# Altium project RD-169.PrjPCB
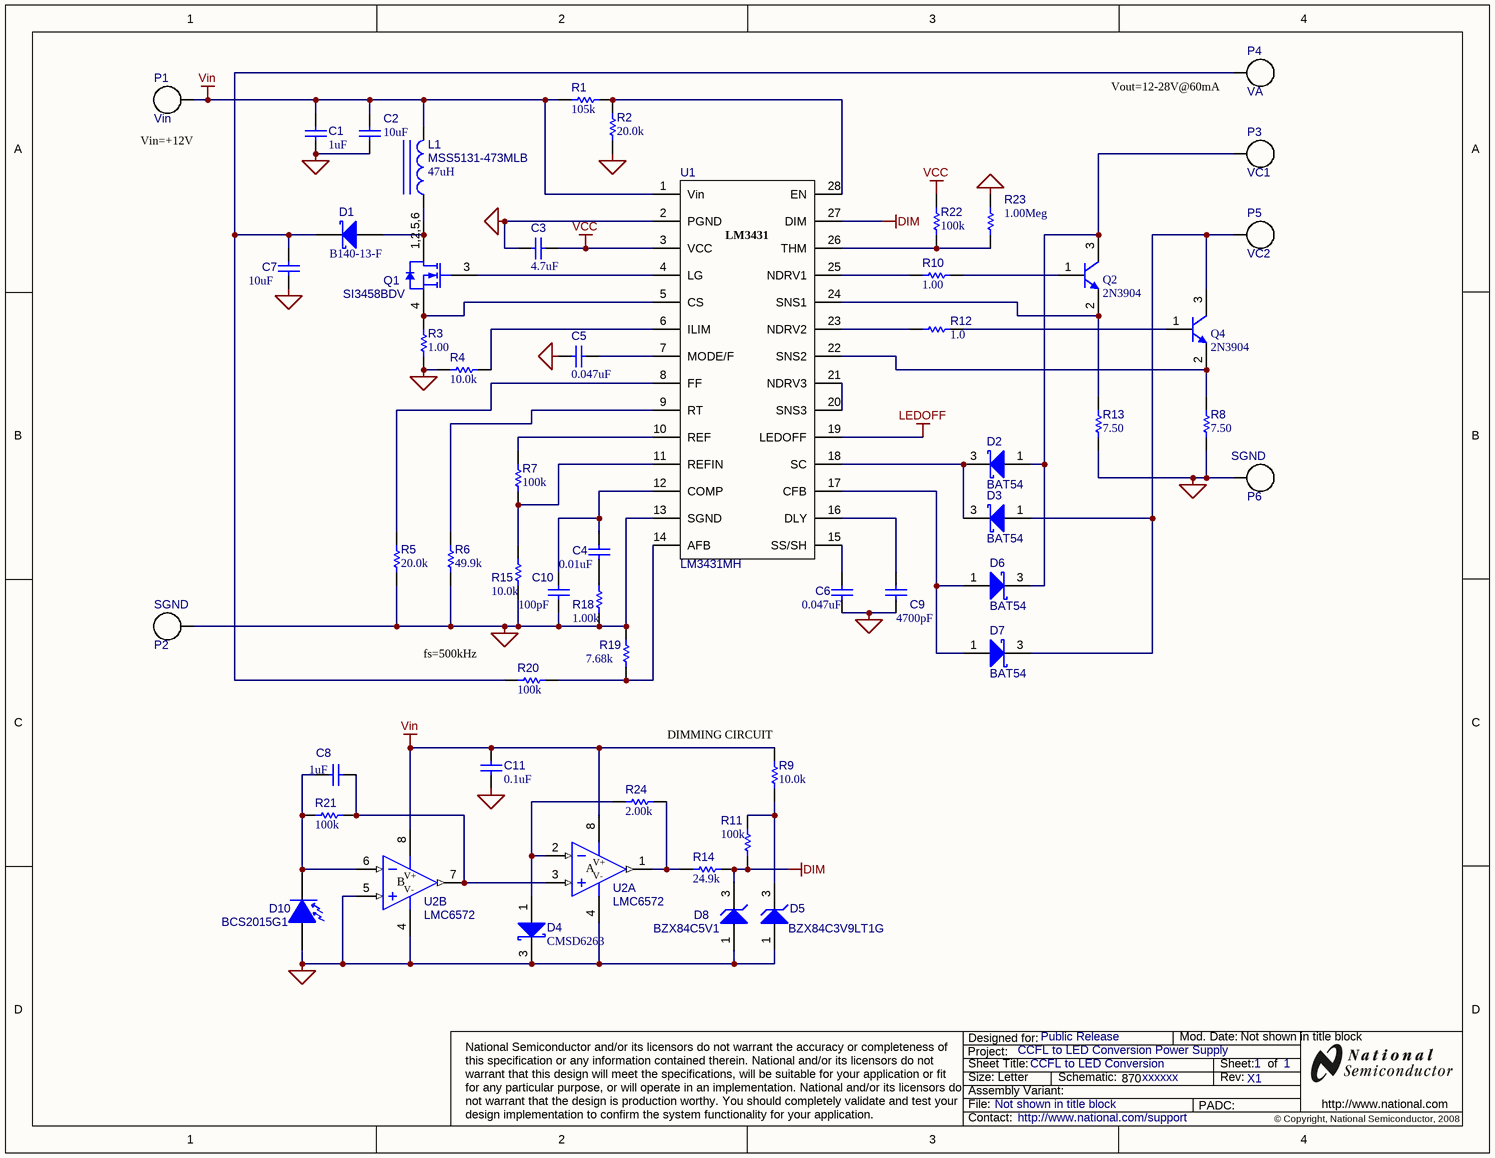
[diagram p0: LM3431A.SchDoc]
TechSupport: http://www.national.com/support; SCH_Rev: X1; PRJ_Title: CCFL to LED Conversion Power Supply; PRJ_Customer: Public Release; PRJ_BasePN: xxxxxx; PCB_MinorRev: -001
1 sheet, 54 parts. Net scope: global (net labels, ports and power ports of the same name join across sheets).

## Sheet LM3431A.SchDoc: CCFL to LED Conversion
size Letter; Date: Not shown in title block; ApprovedBy: Not shown in title block; CheckedBy: Not shown in title block; Author: Not shown in title block; CompanyName: Not shown in title block; DrawnBy: Not shown in title block; Engineer: Not shown in title block; Organization: Not shown in title block; Address1: Not shown in title block; Address2: Not shown in title block; Address3: Not shown in title block; Address4: Not shown in title block; DocumentNumber: 1; Revision: Use project parameter SCH_Rev; SheetNumber: 1; SheetTotal: 1; PageSetup: Record=PageOptions|CenterHorizontal=True|CenterVertical=True|PrintScale=0.97|XCorrection=1.00|YCorrection=1.00|PrintKind=0|BorderSize=5000000|LeftOffset=0|BottomOffset=0|Orientation=2|PaperLength=1000|PaperWidth=1000|Scale=100|PaperSource=15|PrintQuality=600|MediaType=1|DitherType=10|PaperKind=Letter|PrintScaleMode=1

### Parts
C1  value 1uF  [0805]  (hidden comment: C2012X7R1A105K)
C2  value 10uF  [1206]  (hidden comment: C3216X7R1A106M)
C3  value 4.7uF  [1206]  (hidden comment: C3216X5R1A475K)
C4  value 0.01uF  [0805]  (hidden comment: C2012C0G1E103J)
C5  value 0.047uF  [0805]  (hidden comment: C2012X7R2A473K)
C6  value 0.047uF  [0805]  (hidden comment: C2012X7R2A473K)
C7  value 10uF  [1210]  (hidden comment: C3225X7R1E106M)
C8  value 1uF  [0805]  (hidden comment: 0805ZC105MAT2A)
C9  value 4700pF  [0805]  (hidden comment: C2012X7R2A472M)
C10  value 100pF  [0805]  (hidden comment: C2012C0G1H101J)
C11  value 0.1uF  [0805]  (hidden comment: C2012X7R1H104K)
D1  B140-13-F  [SMA]
D2  BAT54  [SOT-23]
D3  BAT54  [SOT-23]
D4  PartNumber: CMSD6263  [SOT-23]
D5  BZX84C3V9LT1G  [SOT-23]
D6  BAT54  [SOT-23]
D7  BAT54  [SOT-23]
D8  BZX84C5V1  [SOT-23]
D10  BCS2015G1  [SMA]
L1  MSS5131-473MLB  value 47uH  [MSS5131]
P1  Vin  [TESTPOINT]  (no BOM)
P2  SGND  [TESTPOINT]  (no BOM)
P3  VC1  [TESTPOINT]  (no BOM)
P4  VA  [TESTPOINT]  (no BOM)
P5  VC2  [TESTPOINT]  (no BOM)
P6  SGND  [TESTPOINT]  (no BOM)
Q1  SI3458BDV  [TSOP-6]
Q2  2N3904  [SOT-23]
Q4  2N3904  [SOT-23]
R1  value 105k  [0805]  (hidden comment: CRCW0805105kFKEA)
R2  value 20.0k  [0805]  (hidden comment: CRCW080520k0FKEA)
R3  value 1.00  [0805]  (hidden comment: CRCW08051R00FNEA)
R4  value 10.0k  [0805]  (hidden comment: CRCW080510k0FKEA)
R5  value 20.0k  [0805]  (hidden comment: CRCW080520k0FKEA)
R6  value 49.9k  [0805]  (hidden comment: CRCW080549k9FKEA)
R7  value 100k  [0805]  (hidden comment: CRCW0805100kFKEA)
R8  value 7.50  [0805]  (hidden comment: CRCW08057R50FNEA)
R9  value 10.0k  [0805]  (hidden comment: CRCW080510k0FKEA)
R10  value 1.00  [0805]  (hidden comment: CRCW08051R00FNEA)
R11  value 100k  [0805]  (hidden comment: CRCW0805100kFKEA)
R12  value 1.0  [0805]  (hidden comment: CRCW08051R00JNEA)
R13  value 7.50  [0805]  (hidden comment: CRCW08057R50FNEA)
R14  value 24.9k  [0805]  (hidden comment: CRCW080524k9FKEA)
R15  value 10.0k  [0805]  (hidden comment: CRCW080510k0FKEA)
R18  value 1.00k  [0805]  (hidden comment: CRCW08051k00FKEA)
R19  value 7.68k  [0805]  (hidden comment: CRCW08057k68FKEA)
R20  value 100k  [0805]  (hidden comment: CRCW0805100kJNEA)
R21  value 100k  [0805]  (hidden comment: CRCW0805100kFKEA)
R22  value 100k  [0805]  (hidden comment: CRCW0805100kFKEA)
R23  value 1.00Meg  [0805]  (hidden comment: CRCW08051M00FKEA)
R24  value 2.00k  [0805]  (hidden comment: CRCW08052k00FKEA)
U1  LM3431MH  [MXA28A]
U2  LMC6572  [M08A]  (parts A,B of 2)

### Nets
DIM: D8.3(K) R11.2 R14.1 U1.27(DIM)
LEDOFF: U1.19(LEDOFF)
NetD4_3: D4.3(K) D5.1(A) D8.1(A) D10.1(A) U2.4(V-) U2.5(IN+)
SGND: C1.2 C2.2 C3.2 C5.2 C6.2 C7.2 C9.2 C10.2 C11.2 P2.1 P6.1 R2.2 R3.2 R4.2 R5.2 R6.2 R8.2 R13.2 R15.2 R18.2 R19.1 R23.1 U1.2(PGND) U1.13(SGND)
VCC: C3.1 R22.1 U1.3(VCC)
Vin: C1.1 C2.1 C11.1 L1.2 P1.1 R1.2 R9.1 U1.1(Vin) U2.8(V+)
NetC4_1: C4.1 C10.1 U1.12(COMP)
NetC4_2: C4.2 R18.1
NetC5_1: C5.1 U1.7(MODE/F)
NetC6_1: C6.1 U1.15(SS/SH)
NetC7_1: C7.1 D1.2(K) P4.1 R20.2
NetC8_1: C8.1 R21.1 U2.3(IN+) U2.7(OUT)
NetC8_2: C8.2 D10.2(K) R21.2 U2.6(IN-)
NetC9_1: C9.1 U1.16(DLY)
NetD1_1: D1.1(A) L1.1 Q1.1,2,5,6(D)
NetD2_1: D2.1(A) D6.3(K) P3.1 Q2.3(C)
NetD2_3: D2.3(K) D3.3(K) U1.18(SC)
NetD3_1: D3.1(A) D7.3(K) P5.1 Q4.3(C)
NetD4_1: D4.1(A) R24.2 U2.2(IN-)
NetD5_3: D5.3(K) R9.2 R11.1
NetD6_1: D6.1(A) D7.1(A) U1.17(CFB)
NetQ1_2: Q1.2(D) Q1.5(D)
NetQ1_3: Q1.3(G) U1.4(LG)
NetQ1_4: Q1.4(S) R3.1 U1.5(CS)
NetQ2_1: Q2.1(B) R10.1
NetQ2_2: Q2.2(E) R13.1 U1.24(SNS1)
NetQ4_1: Q4.1(B) R12.1
NetQ4_2: Q4.2(E) R8.1 U1.22(SNS2)
NetR1_1: R1.1 R2.1 U1.28(EN)
NetR4_1: R4.1 U1.6(ILIM)
NetR5_1: R5.1 U1.8(FF)
NetR6_1: R6.1 U1.9(RT)
NetR7_1: R7.1 U1.10(REF)
NetR7_2: R7.2 R15.1 U1.11(REFIN)
NetR10_2: R10.2 U1.25(NDRV1)
NetR12_2: R12.2 U1.23(NDRV2)
NetR14_2: R14.2 R24.1 U2.1(OUT)
NetR19_2: R19.2 R20.1 U1.14(AFB)
NetR22_2: R22.2 R23.2 U1.26(THM)
NetU1_20: U1.20(SNS3) U1.21(NDRV3)

Not connected (* = marked no-connect by the designer): Q1 6(D)

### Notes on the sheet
- (near P4) Vout=12-28V@60mA
- (near P1) Vin=+12V
- (near R20) fs=500kHz
- (near R9) DIMMING CIRCUIT

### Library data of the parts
C1 = C2012X7R1A105K: Capacitor; Manufacturer: TDK; ESR_Ohm: 0.0075; Polarized: N; TaMax_C: 125; TaMin_C: -55; Tolerance_%: 10; Cap_F: 1.0E-6; Value1: 0.0075Ohm; Value2: 10V; Dielectric: X7R; Characteristics: Ceramic, X7R, 10V, 10%
C2 = C3216X7R1A106M: Capacitor; Manufacturer: TDK; ESR_Ohm: 0.0046; Polarized: N; TaMax_C: 125; TaMin_C: -55; Tolerance_%: 20; VDC_V: 10; Cap_F: 10.0E-6; Value1: 0.0046Ohm; Value2: 10V; Dielectric: X7R; Characteristics: Ceramic, X7R, 10V, 20%
C3 = C3216X5R1A475K: Capacitor; Manufacturer: TDK; ESR_Ohm: 0.0036; Polarized: N; TaMax_C: 85; TaMin_C: -55; Tolerance_%: 10; Cap_F: 4.7E-6; Value1: 0.0036Ohm; Value2: 10V; Dielectric: X5R; Characteristics: Ceramic, X5R, 10V, 10%
C4 = C2012C0G1E103J: Capacitor; Manufacturer: TDK; ESR_Ohm: 0.03; Polarized: N; TaMax_C: 125; TaMin_C: -55; Tolerance_%: 5; VDC_V: 25; Cap_F: 10.0E-9; Value1: 0.03Ohm; Value2: 25V; Dielectric: C0G/NP0; Characteristics: Ceramic, C0G/NP0, 25V, 5%
C5 C6 = C2012X7R2A473K: Capacitor; Manufacturer: TDK; ESR_Ohm: 0.0211; Polarized: N; TaMax_C: 125; TaMin_C: -55; Tolerance_%: 10; VDC_V: 100; Cap_F: 47.0E-9; Value1: 0.0211Ohm; Value2: 100V; Dielectric: X7R; Characteristics: Ceramic, X7R, 100V, 10%
C7 = C3225X7R1E106M: Capacitor; Manufacturer: TDK; ESR_Ohm: 0.0027; IRMS_A: 3; Polarized: N; TaMax_C: 125; TaMin_C: -55; Tolerance_%: 20; VDC_V: 25; Cap_F: 10.0E-6; Value1: 0.0027Ohm; Value2: 25V; Dielectric: X7R; Characteristics: Ceramic, X7R, 25V, 20%
C8 = 0805ZC105MAT2A: Capacitor; Manufacturer: AVX; ESR_Ohm: 0.008; Polarized: N; TaMax_C: 125; TaMin_C: -55; Tolerance_%: 20; VDC_V: 10; Cap_F: 1.0E-6; Value1: 0.008Ohm; Value2: 10V; Dielectric: X7R; Characteristics: Ceramic, X7R, 10V, 20%
C9 = C2012X7R2A472M: Capacitor; Manufacturer: TDK; ESR_Ohm: 0.1198; Polarized: N; TaMax_C: 125; TaMin_C: -55; Tolerance_%: 20; VDC_V: 100; Cap_F: 4.7E-9; Value1: 0.1198Ohm; Value2: 100V; Dielectric: X7R; Characteristics: Ceramic, X7R, 100V, 20%
C10 = C2012C0G1H101J: Capacitor; Manufacturer: TDK; Polarized: N; TaMax_C: 125; TaMin_C: -55; Tolerance_%: 5; VDC_V: 50; Cap_F: 100.0E-12; Value1: Ohm; Value2: 50V; Dielectric: C0G/NP0; Characteristics: Ceramic, C0G/NP0, 50V, 5%
C11 = C2012X7R1H104K: Capacitor; Manufacturer: TDK; Polarized: N; TaMax_C: 125; TaMin_C: -55; Tolerance_%: 10; VDC_V: 50; Cap_F: 100.0E-9; Value1: Ohm; Value2: 50V; Dielectric: X7R; Characteristics: Ceramic, X7R, 50V, 10%
D1 = B140-13: Schottky Diode; Manufacturer: Diodes Inc.; RJC_CperW: 20; Vf_V: 0.5; Io_A: 1; Vr_V: 40; TJMax_C: 150; Value: 0.5V; Value1: 1A; Value2: 40V; Characteristics: Vr = 40V, Io = 1A, Vf = 0.5V
D2 D3 D6 D7 = BAT54-7-F: Schottky Barrier Diode; Manufacturer: Diodes Inc.; Vf_V: 0.24; Value: 0.24V; Io_A: 0.2; Value1: 0.2A; Vr_V: 30; Value2: 30V; TJmax_C: 125; RJC_CperW: 0; Characteristics: Vr = 30V, Io = 0.2A, Vf = 0.24V
D4 = BAT46: Schottky Barrier Diode; Manufacturer: Central Semiconductor; Vf_V: 0.24; Value: 0.24V; Io_A: 0.2; Value1: 0.2A; Vr_V: 30; Value2: 30V; TJmax_C: 125; RJC_CperW: 0; Characteristics: Vr = 70V, Vf = 0.41V
D5 = WB_Zener: Manufacturer: ON Semiconductor; CompType: Zener Diode; Value: 3.9V
D8 = WB_Zener: Manufacturer: Diodes, Inc.; PartNumber: BZX84C5V1-7-F; CompType: Zener; Value: 5.1V
D10 = A10190: Light Emitting Diode; Manufacturer: TDK; CompType: Photodiode
L1 = MSS5131-473MLB: Magnetic-Core Inductor; Manufacturer: Coilcraft Inc.; Characteristics: Shielded Drum Core, 0.38A, 0.32 Ohm; Ind_H: 47.0E-6; DCR_Ohm: 0.32; Value1: 0.32Ohm; Imax_A: 0.38; Value2: 0.38A; Material: Ferrite
P1-P6 = WB_TESTPOINT: TEST POINT.  No entry in BOM.
Q1 = SI3458BDV: N-Chan. Mosfet; Manufacturer: Vishay-Siliconix; ChType: N; Value1: 0.21Ohm; QgTyp_nC: 3.5; Value: 60V; Characteristics: -3.6A, 3.5nC, rDS(on) @ 4.5V =0.105
Q2 Q4 = CMPT3904: NPN Bipolar Transistor; Manufacturer: Central Semiconductor; CompType: BJT; PNP: 0; NPN: 1; Vceo_V: 40; Vcesat1_V: 0.2; Value: 0.2V; Value1: 0.2A; Characteristics: NPN, 0.2A, 40V
R1 = CRCW0805105kFKEA: Resistor; Manufacturer: Vishay-Dale; Tolerance_%: 1; VDC_V: 150; Power_W: 0.125; Res_Ohm: 105000; Value1: 1%; Value2: 0.125W; Characteristics: 1%, 0.125W; EIA_Code: E96
R2 R5 = CRCW080520k0FKEA: Resistor; Manufacturer: Vishay-Dale; Tolerance_%: 1; VDC_V: 150; Power_W: 0.125; Res_Ohm: 20000; Value_Code: 20k0; Value1: 1%; Value2: 0.125W; Characteristics: 1%, 0.125W; EIA_Code: E96
R3 R10 = CRCW08051R00FNEA: Resistor; Manufacturer: Vishay-Dale; Tolerance_%: 1; VDC_V: 150; Power_W: 0.125; Value_Code: 1R00; Value1: 1%; Value2: 0.125W; Characteristics: 1%, 0.125W; EIA_Code: E96
R4 R9 R15 = CRCW080510k0FKEA: Resistor; Manufacturer: Vishay-Dale; Tolerance_%: 1; VDC_V: 150; Power_W: 0.125; Res_Ohm: 10000; Value_Code: 10k0; Value1: 1%; Value2: 0.125W; Characteristics: 1%, 0.125W; EIA_Code: E96
R6 = CRCW080549k9FKEA: Resistor; Manufacturer: Vishay-Dale; Tolerance_%: 1; VDC_V: 150; Power_W: 0.125; Res_Ohm: 49900; Value_Code: 49k9; Value1: 1%; Value2: 0.125W; Characteristics: 1%, 0.125W; EIA_Code: E96
R7 R11 R21 R22 = CRCW0805100kFKEA: Resistor; Manufacturer: Vishay-Dale; Tolerance_%: 1; VDC_V: 150; Power_W: 0.125; Res_Ohm: 100000; Value1: 1%; Value2: 0.125W; Characteristics: 1%, 0.125W; EIA_Code: E96
R8 R13 = CRCW08057R50FNEA: Resistor; Manufacturer: Vishay-Dale; Tolerance_%: 1; VDC_V: 150; Power_W: 0.125; Res_Ohm: 7.5; Value_Code: 7R50; Value1: 1%; Value2: 0.125W; Characteristics: 1%, 0.125W; EIA_Code: E96
R12 = CRCW08051R00JNEA: Resistor; Manufacturer: Vishay-Dale; Tolerance_%: 5; VDC_V: 150; Power_W: 0.125; Res_Ohm: 1; Value_Code: 1R00; Value1: 5%; Value2: 0.125W; Characteristics: 5%, 0.125W; EIA_Code: E24
R14 = CRCW080524k9FKEA: Resistor; Manufacturer: Vishay-Dale; Tolerance_%: 1; VDC_V: 150; Power_W: 0.125; Res_Ohm: 24900; Value_Code: 24k9; Value1: 1%; Value2: 0.125W; Characteristics: 1%, 0.125W; EIA_Code: E96
R18 = CRCW08051k00FKEA: Resistor; Manufacturer: Vishay-Dale; Tolerance_%: 1; VDC_V: 150; Power_W: 0.125; Res_Ohm: 1000; Value_Code: 1k00; Value1: 1%; Value2: 0.125W; Characteristics: 1%, 0.125W; EIA_Code: E96
R19 = CRCW08057k68FKEA: Resistor; Manufacturer: Vishay-Dale; Tolerance_%: 1; VDC_V: 150; Power_W: 0.125; Res_Ohm: 7680; Value_Code: 7k68; Value1: 1%; Value2: 0.125W; Characteristics: 1%, 0.125W; EIA_Code: E96
R20 = CRCW0805100kJNEA: Resistor; Manufacturer: Vishay-Dale; Tolerance_%: 5; VDC_V: 150; Power_W: 0.125; Res_Ohm: 100000; Value1: 5%; Value2: 0.125W; Characteristics: 5%, 0.125W; EIA_Code: E24
R23 = CRCW08051M00FKEA: Resistor; Manufacturer: Vishay-Dale; Tolerance_%: 1; VDC_V: 150; Power_W: 0.125; Res_Ohm: 1000000; Value_Code: 1M00; Value1: 1%; Value2: 0.125W; Characteristics: 1%, 0.125W; EIA_Code: E96
R24 = CRCW08052k00FKEA: Resistor; Manufacturer: Vishay-Dale; Tolerance_%: 1; VDC_V: 150; Power_W: 0.125; Res_Ohm: 2000; Value_Code: 2k00; Value1: 1%; Value2: 0.125W; Characteristics: 1%, 0.125W; EIA_Code: E96
U1 = LM3431: 3-Channel Constant Current LED Driver with Integrated Boost Controller; Manufacturer: National Semiconductor; CompType: Switcher; base_pn: LM5642
U2 = LMC6572AIM: Dual CMOS Low Voltage (2.7V and 3V) R-R Out Op Amp; Manufacturer: National Semiconductor; CompType: OpAmp IC; TaMin_C: -40.0; TaMax_C: 85.0

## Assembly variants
-100A: all parts fitted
